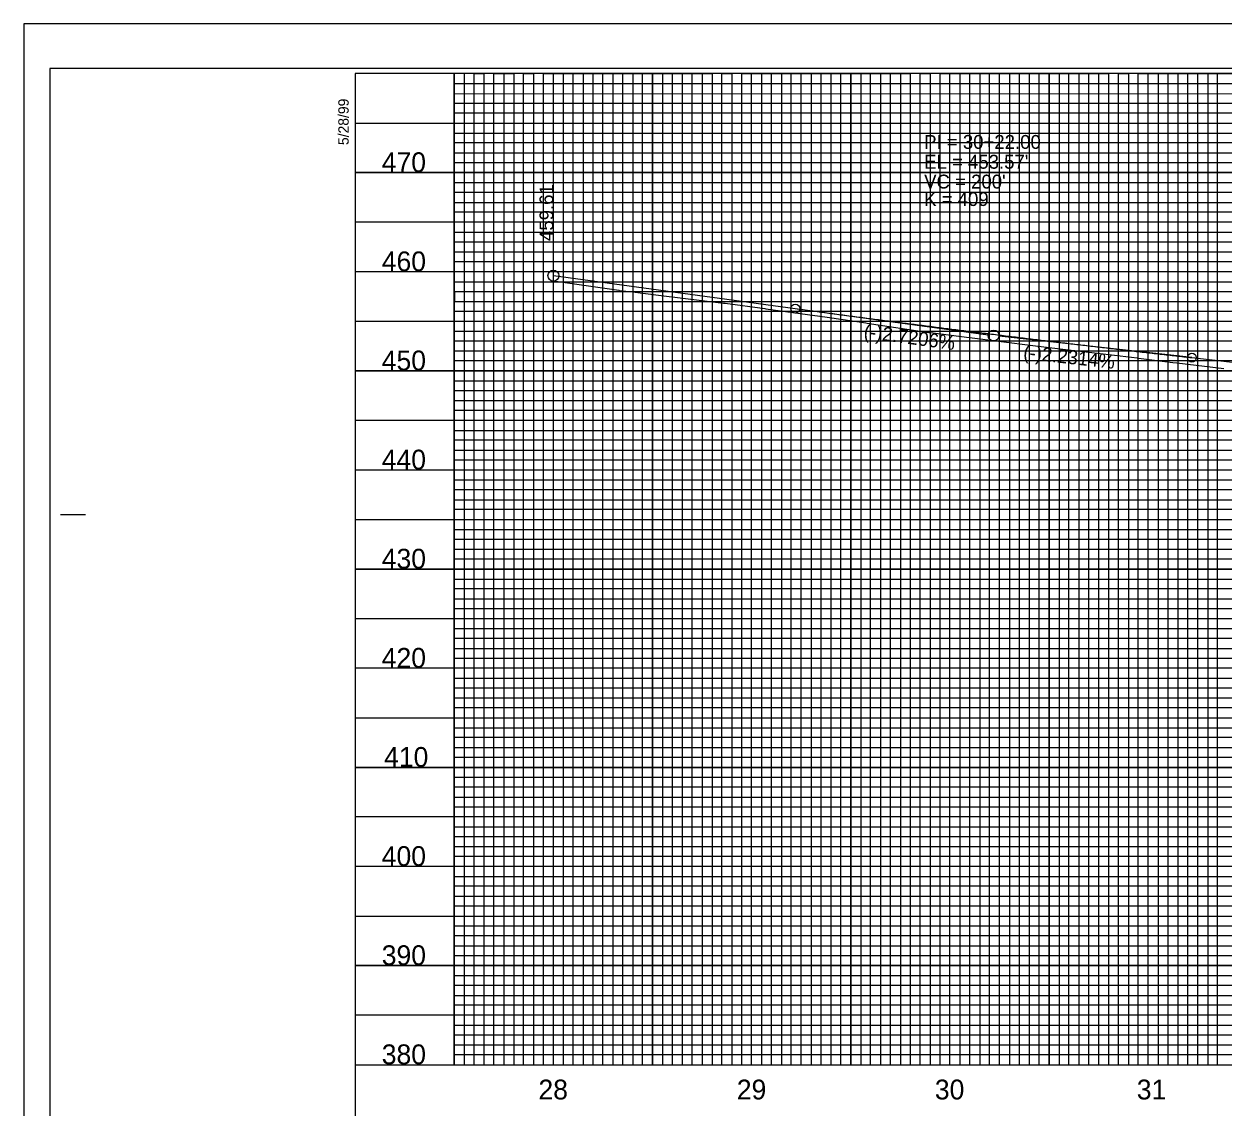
# Model space of a CAD drawing. Extents: x 571503 to 593215, y -77195 to -51828.
# Drawn here: x 582330 to 582935, y -73461 to -72915 of the extents above; entities that cross this region are included whole.
import ezdxf

# ---------------------------------------------------------------- set-up
doc = ezdxf.new("R2010")
doc.units = 0
for name, color, linetype in [('Exist Vertical Profile Ground Line', 7, 'Continuous'), ('Exist Vertical Profile Horizontal Axis Label Major', 7, 'Continuous'), ('Exist Vertical Profile Vertical Axis Label', 7, 'Continuous'), ('Prop Vertical Profile Curve Label', 7, 'Continuous'), ('Prop Vertical Profile Grade', 7, 'Continuous'), ('Prop Vertical Profile Grade Label', 7, 'Continuous'), ('Prop VPI Label', 7, 'Continuous'), ('Sheet Cutting Line CELL', 7, 'Continuous'), ('Sheet DOT Grid CELL', 7, 'Continuous'), ('Sheet Layout Profile Border Port 1', 7, 'Continuous'), ('Sheet Plot Border Inside CELL', 7, 'Continuous'), ('Sheet Plot Border Outside CELL', 7, 'Continuous'), ('Sheet Profile CELL', 7, 'Continuous'), ('Sheet Profile Grid Major CELL', 7, 'Continuous'), ('Sheet Profile Grid Middle CELL', 7, 'Continuous'), ('Sheet Profile Grid Minor CELL', 7, 'Continuous')]:
    doc.layers.add(name, color=color, linetype=linetype)

msp = doc.modelspace()

# ---------------------------------------------------------------- linework, layer by layer
at = {"layer": 'Exist Vertical Profile Ground Line'}
msp.add_lwpolyline([(582596.98, -73044.72), (582598.11, -73044.88), (582598.21, -73044.9), (582630.06, -73049.45), (582630.19, -73049.46), (582636.81, -73050.26), (582651.42, -73052.05), (582682.7, -73055.88), (582683.59, -73055.98), (582703.61, -73058.68), (582704.18, -73058.76), (582735.04, -73062.93), (582736.19, -73063.1), (582754.57, -73065.87), (582755.17, -73065.96), (582786.39, -73070.65), (582787.09, -73070.76), (582806.61, -73073.24), (582806.83, -73073.27), (582838.74, -73077.32), (582838.76, -73077.32), (582859.53, -73079.8), (582860.02, -73079.85), (582891.32, -73083.58), (582892.04, -73083.65), (582909.37, -73085.81), (582911.47, -73086), (582935.09, -73088.91)], dxfattribs=at)
at = {"layer": 'Prop Vertical Profile Curve Label'}
for centre in [(582718.98, -73058.64), (582918.98, -73083.4)]:
    msp.add_circle(centre, 2.25, dxfattribs=at)
at = {"layer": 'Prop Vertical Profile Grade'}
for p, q in [((582596.98, -73042.05), (582718.98, -73058.64)), ((582918.98, -73083.4), (583161.98, -73110.51))]:
    msp.add_line(p, q, dxfattribs=at)
msp.add_spline([(582718.98, -73058.64), (582722.98, -73059.18), (582726.98, -73059.73), (582730.98, -73060.26), (582734.98, -73060.8), (582738.98, -73061.34), (582742.98, -73061.87), (582746.98, -73062.4), (582750.98, -73062.93), (582754.98, -73063.46), (582758.98, -73063.98), (582762.98, -73064.51), (582766.98, -73065.03), (582770.98, -73065.55), (582774.98, -73066.07), (582778.98, -73066.58), (582782.98, -73067.1), (582786.98, -73067.61), (582790.98, -73068.12), (582794.98, -73068.63), (582798.98, -73069.13), (582802.98, -73069.64), (582806.98, -73070.14), (582810.98, -73070.64), (582814.98, -73071.14), (582818.98, -73071.63), (582822.98, -73072.13), (582826.98, -73072.62), (582830.98, -73073.11), (582834.98, -73073.6), (582838.98, -73074.08), (582842.98, -73074.57), (582846.98, -73075.05), (582850.98, -73075.53), (582854.98, -73076.01), (582858.98, -73076.49), (582862.98, -73076.96), (582866.98, -73077.43), (582870.98, -73077.91), (582874.98, -73078.37), (582878.98, -73078.84), (582882.98, -73079.31), (582886.98, -73079.77), (582890.98, -73080.23), (582894.98, -73080.69), (582898.98, -73081.15), (582902.98, -73081.6), (582906.98, -73082.05), (582910.98, -73082.5), (582914.98, -73082.95), (582918.98, -73083.4)], degree=3, dxfattribs=at)
at = {"layer": 'Prop VPI Label'}
for p, q in [((582718.98, -73058.64), (582816.26, -73071.87)), ((582918.98, -73083.4), (582821.72, -73072.55))]:
    msp.add_line(p, q, dxfattribs=at)
for centre in [(582596.98, -73042.05), (582818.98, -73072.24)]:
    msp.add_circle(centre, 2.75, dxfattribs=at)
at = {"layer": 'Sheet Cutting Line CELL'}
for p, q in [((584013.98, -72915.09), (582329.98, -72915.09)), ((582329.98, -72915.09), (582329.98, -74015.09))]:
    msp.add_line(p, q, dxfattribs=at)
at = {"layer": 'Sheet DOT Grid CELL'}
for p, q in [((582546.98, -73440.09), (582546.98, -72940.09)), ((582596.98, -73440.09), (582596.98, -72940.09)), ((582646.98, -73440.09), (582646.98, -72940.09)), ((582696.98, -73440.09), (582696.98, -72940.09)), ((582746.98, -73440.09), (582746.98, -72940.09)), ((582796.98, -73440.09), (582796.98, -72940.09)), ((582846.98, -73440.09), (582846.98, -72940.09)), ((582896.98, -73440.09), (582896.98, -72940.09)), ((583796.93, -72990.09), (582496.98, -72990.09)), ((583796.93, -73040.09), (582496.98, -73040.09)), ((583996.98, -73090.09), (582496.98, -73090.09)), ((583996.98, -73140.09), (582496.98, -73140.09)), ((583996.98, -73190.09), (582496.98, -73190.09)), ((583996.98, -73240.09), (582496.98, -73240.09)), ((583996.98, -73290.09), (582496.98, -73290.09)), ((583996.98, -73340.09), (582496.98, -73340.09)), ((583996.98, -73390.09), (582496.98, -73390.09))]:
    msp.add_line(p, q, dxfattribs=at)
at = {"layer": 'Sheet Layout Profile Border Port 1'}
msp.add_lwpolyline([(582546.98, -72940.09), (582546.98, -73440.09), (583946.98, -73440.09), (583946.98, -73077.64), (583796.93, -73077.64), (583796.93, -72940.09)], close=True, dxfattribs=at)
at = {"layer": 'Sheet Plot Border Inside CELL'}
msp.add_lwpolyline([(582342.98, -73992.64), (584009.48, -73992.64), (584009.48, -72937.54), (582342.98, -72937.54)], close=True, dxfattribs=at)
at = {"layer": 'Sheet Plot Border Outside CELL'}
msp.add_lwpolyline([(582329.98, -74015.09), (584013.98, -74015.09), (584013.98, -72915.09), (582329.98, -72915.09)], close=True, dxfattribs=at)
at = {"layer": 'Sheet Profile CELL'}
for p, q in [((582348.48, -73162.59), (582360.98, -73162.59)), ((582496.98, -73440.09), (583996.98, -73440.09))]:
    msp.add_line(p, q, dxfattribs=at)
msp.add_lwpolyline([(583996.98, -72940.09), (582496.98, -72940.09), (582496.98, -73990.09), (583996.98, -73990.09)], close=True, dxfattribs=at)
at = {"layer": 'Sheet Profile Grid Major CELL'}
for points in [[(582546.98, -72940.09), (582546.98, -73440.09), (582596.98, -73440.09), (582596.98, -72940.09), (582646.98, -72940.09), (582646.98, -73440.09), (582696.98, -73440.09), (582696.98, -72940.09), (582746.98, -72940.09), (582746.98, -73440.09), (582796.98, -73440.09), (582796.98, -72940.09), (582846.98, -72940.09), (582846.98, -73440.09), (582896.98, -73440.09), (582896.98, -72940.09), (582946.98, -72940.09)], [(582496.98, -72990.09), (583796.98, -72990.09)], [(583796.98, -73040.09), (582496.98, -73040.09), (582496.98, -73090.09), (583996.98, -73090.09)], [(583996.98, -73140.09), (582496.98, -73140.09), (582496.98, -73190.09), (583996.98, -73190.09)], [(583996.98, -73240.09), (582496.98, -73240.09), (582496.98, -73290.09), (583996.98, -73290.09)], [(583996.98, -73340.09), (582496.98, -73340.09), (582496.98, -73340.09), (582496.98, -73390.09), (583996.98, -73390.09)]]:
    msp.add_lwpolyline(points, dxfattribs=at)
at = {"layer": 'Sheet Profile Grid Middle CELL'}
msp.add_line((582496.98, -72965.09), (583796.93, -72965.09), dxfattribs=at)
for points in [[(582571.98, -72940.09), (582571.98, -73440.09), (582621.98, -73440.09), (582621.98, -72940.09), (582671.98, -72940.09), (582671.98, -73440.09), (582721.98, -73440.09), (582721.98, -72940.09), (582771.98, -72940.09), (582771.98, -73440.09), (582821.98, -73440.09), (582821.98, -72940.09), (582871.98, -72940.09), (582871.98, -73440.09), (582921.98, -73440.09), (582921.98, -72940.09), (582971.98, -72940.09)], [(583796.98, -73015.09), (582496.98, -73015.09), (582496.98, -73065.09), (583796.98, -73065.09)], [(583996.98, -73115.09), (582496.98, -73115.09), (582496.98, -73165.09), (583821.98, -73165.09)], [(583996.98, -73215.09), (582496.98, -73215.09), (582496.98, -73265.09), (583996.98, -73265.09)], [(583996.98, -73315.09), (582496.98, -73315.09), (582496.98, -73365.09), (583996.98, -73365.09)], [(583996.98, -73415.09), (582496.98, -73415.09)]]:
    msp.add_lwpolyline(points, dxfattribs=at)
at = {"layer": 'Sheet Profile Grid Minor CELL'}
for p, q in [((582546.98, -72945.09), (583796.98, -72945.09)), ((582546.98, -72950.09), (582546.98, -72950.09)), ((583796.98, -72950.09), (582546.98, -72950.44)), ((582546.98, -72955.09), (583796.98, -72955.09)), ((583796.93, -73075.09), (582546.98, -73075.09)), ((583946.98, -73080.09), (582546.98, -73080.09)), ((583946.98, -73085.09), (582546.98, -73085.09)), ((582546.98, -73095.09), (583946.98, -73095.09)), ((583946.98, -73100.09), (582546.98, -73100.09)), ((582546.98, -73105.09), (583946.98, -73105.09)), ((583946.98, -73125.09), (582546.98, -73125.09)), ((582546.98, -73130.09), (583946.98, -73130.09)), ((583946.98, -73150.09), (582546.98, -73150.09)), ((582546.98, -73155.09), (583946.98, -73155.09)), ((583946.98, -73175.09), (582546.98, -73175.09)), ((582546.98, -73180.09), (583946.98, -73180.09)), ((583946.98, -73185.09), (582546.98, -73185.09)), ((582546.98, -73195.09), (583946.98, -73195.09)), ((583946.98, -73200.09), (582546.98, -73200.09)), ((582546.98, -73205.09), (583946.98, -73205.09)), ((583946.98, -73210.09), (582546.98, -73210.09)), ((582546.98, -73220.09), (583946.98, -73220.09)), ((583946.98, -73225.09), (582546.98, -73225.09)), ((582546.98, -73230.09), (583946.98, -73230.09)), ((583946.98, -73235.09), (582546.98, -73235.09)), ((582546.98, -73245.09), (583946.98, -73245.09)), ((583946.98, -73250.09), (582546.98, -73250.09)), ((582546.98, -73255.09), (583946.98, -73255.09)), ((583946.98, -73260.09), (582546.98, -73260.09)), ((582546.98, -73270.09), (583946.98, -73270.09)), ((583946.98, -73275.09), (582546.98, -73275.09)), ((582546.98, -73280.09), (583946.98, -73280.09)), ((583946.98, -73285.09), (582546.98, -73285.09)), ((582546.98, -73295.09), (583946.98, -73295.09)), ((583946.98, -73300.09), (582546.98, -73300.09)), ((582546.98, -73305.09), (583946.98, -73305.09)), ((583946.98, -73310.09), (582546.98, -73310.09)), ((582546.98, -73320.09), (583946.98, -73320.09)), ((583946.98, -73325.09), (582546.98, -73325.09)), ((583946.98, -73330.09), (582546.98, -73330.09)), ((583946.98, -73335.09), (582546.98, -73335.09)), ((582546.98, -73345.09), (583946.98, -73345.09)), ((583946.98, -73350.09), (582546.98, -73350.09)), ((582546.98, -73355.09), (583946.98, -73355.09)), ((583946.98, -73360.09), (582546.98, -73360.09)), ((582546.98, -73370.09), (583946.98, -73370.09)), ((583946.98, -73375.09), (582546.98, -73375.09)), ((582546.98, -73380.09), (583946.98, -73380.09)), ((583946.98, -73385.09), (582546.98, -73385.09)), ((582546.98, -73395.09), (583946.98, -73395.09)), ((583946.98, -73400.09), (582546.98, -73400.09)), ((582546.98, -73405.09), (583946.98, -73405.09)), ((583946.98, -73410.09), (582546.98, -73410.09)), ((582546.98, -73420.09), (583946.98, -73420.09)), ((583946.98, -73425.09), (582546.98, -73425.09)), ((582546.98, -73430.09), (583946.98, -73430.09))]:
    msp.add_line(p, q, dxfattribs=at)
for points in [[(582551.98, -72940.09), (582551.98, -73440.09), (582556.98, -73440.09), (582556.98, -72940.09), (582561.98, -72940.09), (582561.98, -73440.09), (582566.98, -73440.09), (582566.98, -72940.09), (582576.98, -72940.09), (582576.98, -73440.09), (582581.98, -73440.09), (582581.98, -72940.09), (582586.98, -72940.09), (582586.98, -73440.09), (582591.98, -73440.09), (582601.98, -73440.09), (582606.98, -73440.09), (582606.98, -72940.09), (582611.98, -72940.09), (582611.98, -73440.09), (582616.98, -73440.09), (582616.98, -72940.09), (582626.98, -72940.09), (582626.98, -73440.09), (582631.98, -73440.09), (582631.98, -72940.09), (582636.98, -72940.09), (582636.98, -73440.09), (582641.98, -73440.09), (582641.98, -72940.09), (582651.98, -72940.09), (582651.98, -73440.09), (582656.98, -73440.09), (582656.98, -72940.09), (582661.98, -72940.09), (582661.98, -73440.09), (582666.98, -73440.09), (582666.98, -72940.09), (582676.98, -72940.09), (582676.98, -73440.09), (582681.98, -73440.09), (582681.98, -72940.09), (582686.98, -72940.09), (582686.98, -73440.09), (582691.98, -73440.09), (582691.98, -72940.09), (582701.98, -72940.09), (582701.98, -73440.09), (582706.98, -73440.09), (582706.98, -72940.09), (582711.98, -72940.09), (582711.98, -73440.09), (582716.98, -73440.09), (582716.98, -72940.09), (582726.98, -72940.09), (582726.98, -73440.09), (582731.98, -73440.09), (582731.98, -72940.09), (582736.98, -72940.09), (582736.98, -73440.09), (582741.98, -73440.09), (582741.98, -72940.09), (582751.98, -72940.09), (582751.98, -73440.09), (582756.98, -73440.09), (582756.98, -72940.09), (582761.98, -72940.09), (582761.98, -73440.09)], [(582591.98, -73440.09), (582591.98, -72940.09), (582601.98, -72940.09), (582601.98, -73440.09)], [(582761.98, -73440.09), (582766.98, -73440.09), (582766.98, -72940.09), (582776.98, -72940.09), (582776.98, -73440.09), (582781.98, -73440.09), (582781.98, -72940.09), (582786.98, -72940.09), (582786.98, -73440.09), (582791.98, -73440.09), (582791.98, -72940.09), (582801.98, -72940.09), (582801.98, -73440.09), (582806.98, -73440.09), (582806.98, -72940.09), (582811.98, -72940.09), (582811.98, -73440.09), (582816.98, -73440.09), (582816.98, -72940.09), (582826.98, -72940.09), (582826.98, -73440.09), (582831.98, -73440.09), (582831.98, -72940.09), (582836.98, -72940.09), (582836.98, -73440.09), (582841.98, -73440.09), (582841.98, -72940.09), (582851.98, -72940.09), (582851.98, -73440.09), (582856.98, -73440.09), (582856.98, -72940.09), (582861.98, -72940.09), (582861.98, -73440.09), (582866.98, -73440.09), (582866.98, -72940.09), (582876.98, -72940.09), (582876.98, -73440.09), (582881.98, -73440.09), (582881.98, -72940.09), (582886.98, -72940.09), (582886.98, -73440.09), (582891.98, -73440.09), (582891.98, -72940.09), (582901.98, -72940.09), (582901.98, -73440.09), (582906.98, -73440.09), (582906.98, -72940.09), (582911.98, -72940.09), (582911.98, -73440.09), (582916.98, -73440.09), (582916.98, -72940.09), (582926.98, -72940.09), (582926.98, -73440.09), (582931.98, -73440.09), (582931.98, -72940.09), (582936.98, -72940.09)], [(583796.98, -72960.09), (582546.98, -72960.09), (582546.98, -72970.09), (583796.98, -72970.09)], [(583796.93, -72975.09), (582546.98, -72975.09), (582546.98, -72980.09), (583796.98, -72980.09)], [(583796.98, -72985.09), (582546.98, -72985.09), (582546.98, -72995.09), (583796.98, -72995.09)], [(583796.98, -73000.09), (582546.98, -73000.09), (582546.98, -73005.09), (583796.98, -73005.09)], [(583796.98, -73010.09), (582546.98, -73010.09), (582546.98, -73020.09), (583796.98, -73020.09)], [(583796.98, -73025.09), (582546.98, -73025.09), (582546.98, -73030.09), (583796.98, -73030.09)], [(583796.98, -73035.09), (582546.98, -73035.09), (582546.98, -73045.09), (583796.98, -73045.09)], [(583796.98, -73050.19), (582547.08, -73050.19), (582547.08, -73055.09), (583796.98, -73055.09)], [(583796.98, -73060.09), (582546.98, -73060.09), (582546.98, -73070.09), (583796.98, -73070.09)], [(583946.98, -73110.09), (582546.98, -73110.09), (582546.98, -73120.09), (583946.98, -73120.09)], [(583946.98, -73135.09), (582546.98, -73135.09), (582546.98, -73145.09), (583946.98, -73145.09)], [(583946.98, -73160.09), (582546.98, -73160.09), (582546.98, -73170.09), (583946.98, -73170.09)], [(583946.98, -73435.09), (582546.98, -73435.09)]]:
    msp.add_lwpolyline(points, dxfattribs=at)

# ---------------------------------------------------------------- texts
at = {"layer": 'Exist Vertical Profile Horizontal Axis Label Major'}
for s, p in [('28', (582589.45, -73457.59)), ('29', (582689.49, -73457.59)), ('30', (582789.37, -73457.59)), ('31', (582891.21, -73457.59))]:
    msp.add_text(s, height=10, dxfattribs=at).set_placement(p)
at = {"layer": 'Exist Vertical Profile Vertical Axis Label'}
for s, p in [('470', (582510.42, -72989.84)), ('460', (582510.42, -73039.84)), ('450', (582510.42, -73089.84)), ('440', (582510.42, -73139.84)), ('430', (582510.42, -73189.84)), ('420', (582510.42, -73239.84)), ('410', (582511.61, -73289.84)), ('400', (582510.42, -73339.84)), ('390', (582510.42, -73389.84)), ('380', (582510.42, -73439.84))]:
    msp.add_text(s, height=10, dxfattribs=at).set_placement(p)
at = {"layer": 'Prop Vertical Profile Curve Label'}
for s, p in [("VC = 200'", (582783.98, -72998.1)), ('K = 409', (582783.98, -73006.91))]:
    msp.add_text(s, height=7, dxfattribs=at).set_placement(p)
at = {"layer": 'Prop Vertical Profile Grade Label'}
for s, rotation, p in [('(-)2.7206%', 352.25356, (582753.21, -73073.39)), ('(-)2.2314%', 353.63396, (582833.75, -73083.95))]:
    msp.add_text(s, height=7, rotation=rotation, dxfattribs=at).set_placement(p)
at = {"layer": 'Prop VPI Label'}
for s, p in [('PI = 30+22.00', (582783.98, -72978.1)), ("EL = 453.57'", (582783.98, -72988.1))]:
    msp.add_text(s, height=7, dxfattribs=at).set_placement(p)
msp.add_text('459.61', height=7, rotation=90, dxfattribs=at).set_placement((582596.98, -73024.55))
at = {"layer": 'Sheet Profile CELL'}
msp.add_text('5/28/99', height=5.25, rotation=90, dxfattribs=at).set_placement((582493.75, -72976.18))

doc.saveas('drawing.dxf')
